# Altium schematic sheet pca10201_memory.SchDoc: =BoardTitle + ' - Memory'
size A3; Organization: Nordic Semiconductor; DocumentNumber: 6; SheetNumber: 6; SheetTotal: 10; CompanyName: Nordic Semiconductor; DocumentSize: A3
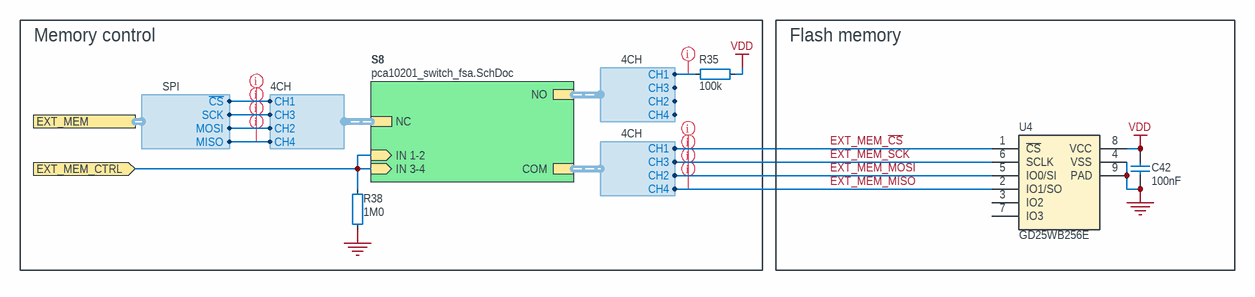
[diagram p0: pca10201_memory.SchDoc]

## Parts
C42  100nF  [CAPC0603X03L_C]
R35  100k  [RESC0603X03L_C]
R38  1M0  [RESC0603X03L_C]
U4  GD25WB256E  [SON127P800X80_HS-9N]

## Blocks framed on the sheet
Memory control: R35 R38
Flash memory: C42 U4

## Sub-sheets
S8 = pca10201_switch_fsa.SchDoc: IN 1-2 (in), COM (harness 4CH), NC (harness 4CH), NO (harness 4CH), IN 3-4 (in)

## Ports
EXT_MEM (harness SPI), EXT_MEM_CTRL (in)

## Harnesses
4CH: CH1, CH2, CH3, CH4
SPI: SCK, ~{CS}, MOSI, MISO

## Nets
GND: C42.1 R38.1 U4.4(VSS) U4.9(PAD)
VDD: C42.2 R35.2 U4.8(VCC)
EXT_MEM_~{CS}: U4.1(~{CS}) ; sheet S8/COM.CH1
EXT_MEM_CTRL: R38.2 ; port EXT_MEM_CTRL, sheet S8/IN 1-2, sheet S8/IN 3-4
EXT_MEM_MISO: U4.2(IO1/SO) ; sheet S8/COM.CH4
EXT_MEM_MOSI: U4.5(IO0/SI) ; sheet S8/COM.CH2
EXT_MEM_SCK: U4.6(SCLK) ; sheet S8/COM.CH3
NetR35_1: R35.1 ; sheet S8/NO.CH1
(unnamed): port EXT_MEM.SCK, sheet S8/NC.CH3
(unnamed): port EXT_MEM.~{CS}, sheet S8/NC.CH1  [a separate net that carries the same name]
(unnamed): port EXT_MEM.MOSI, sheet S8/NC.CH2  [a separate net that carries the same name]
(unnamed): port EXT_MEM.MISO, sheet S8/NC.CH4  [a separate net that carries the same name]

Not connected (* = marked no-connect by the designer): U4 3(IO2) 7(IO3)

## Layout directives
net class GPIO: (no net found under the mark), EXT_MEM_MISO, EXT_MEM_MOSI, EXT_MEM_SCK, EXT_MEM_~{CS}, NetR35_1

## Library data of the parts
C42 = C0201-100n: Capacitor, X5R, ±10%, 100nF, 16V; Manufacturer: N.A.; Part number IPS: 00000001248, 00000002505; Part number Norautron: 262071862; Part number NEMS: 100200078; Pad Count: 2; Component Status: Active
R35 = R0201-100k: Resistor, ±1%, 0.05W; Manufacturer: N.A.; Part number IPS: 00000001419; Part number Norautron: 26108487; Part number NEMS: 100100080; Pad Count: 2; Note: Chip Res 1%; Component Status: Active
R38 = R0201-1M0: Resistor, ±1%, 0.05W; Manufacturer: N.A.; Part number IPS: 00000001418; Part number Norautron: 26107108; Part number NEMS: 100100093; Note: Chip Res 1%; Pad Count: 2; Component Status: Active
U4 = GD25WB256EYIGR: Quad Serial Flash, 256Mbit, 104MHz, 1.65V - 3.6V; Manufacturer: GigaDevice; Part number NEMS: 101900774; Note: a med; Artikkelnr Noca: N.A.; Pad Count: 8; Component Status: Active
